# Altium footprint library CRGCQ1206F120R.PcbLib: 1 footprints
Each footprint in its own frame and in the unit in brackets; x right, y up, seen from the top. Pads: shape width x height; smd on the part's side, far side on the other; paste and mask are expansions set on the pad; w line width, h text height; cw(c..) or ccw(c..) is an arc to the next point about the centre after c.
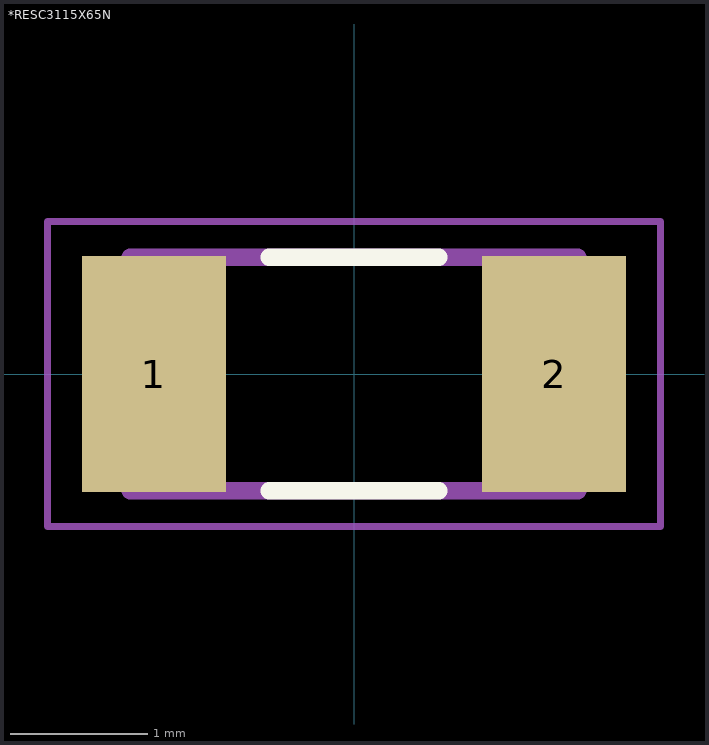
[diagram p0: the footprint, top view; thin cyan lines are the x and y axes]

## *RESC3115X65N [mm]
pads (2):
  rect 1.05x1.72 smd: 1(-1.46,0) 2(1.46,0)
Top Overlay:
  lines w0.127: -0.62,-0.85 0.62,-0.85 ; -0.62,0.85 0.62,0.85
Mechanical 4:
  lines w0.127: -1.63,-0.85 -1.63,0.85 ; -1.63,-0.85 1.63,-0.85 ; -1.63,-0.85 -1.63,0.85 ; -1.63,-0.85 1.63,-0.85 ; -1.63,0.85 1.63,0.85 ; -1.63,0.85 1.63,0.85 ; 1.63,-0.85 1.63,0.85 ; 1.63,-0.85 1.63,0.85
Mechanical 16:
  lines w0.05: -2.235,-1.112 -2.235,1.112 2.235,1.112 2.235,-1.112 -2.235,-1.112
